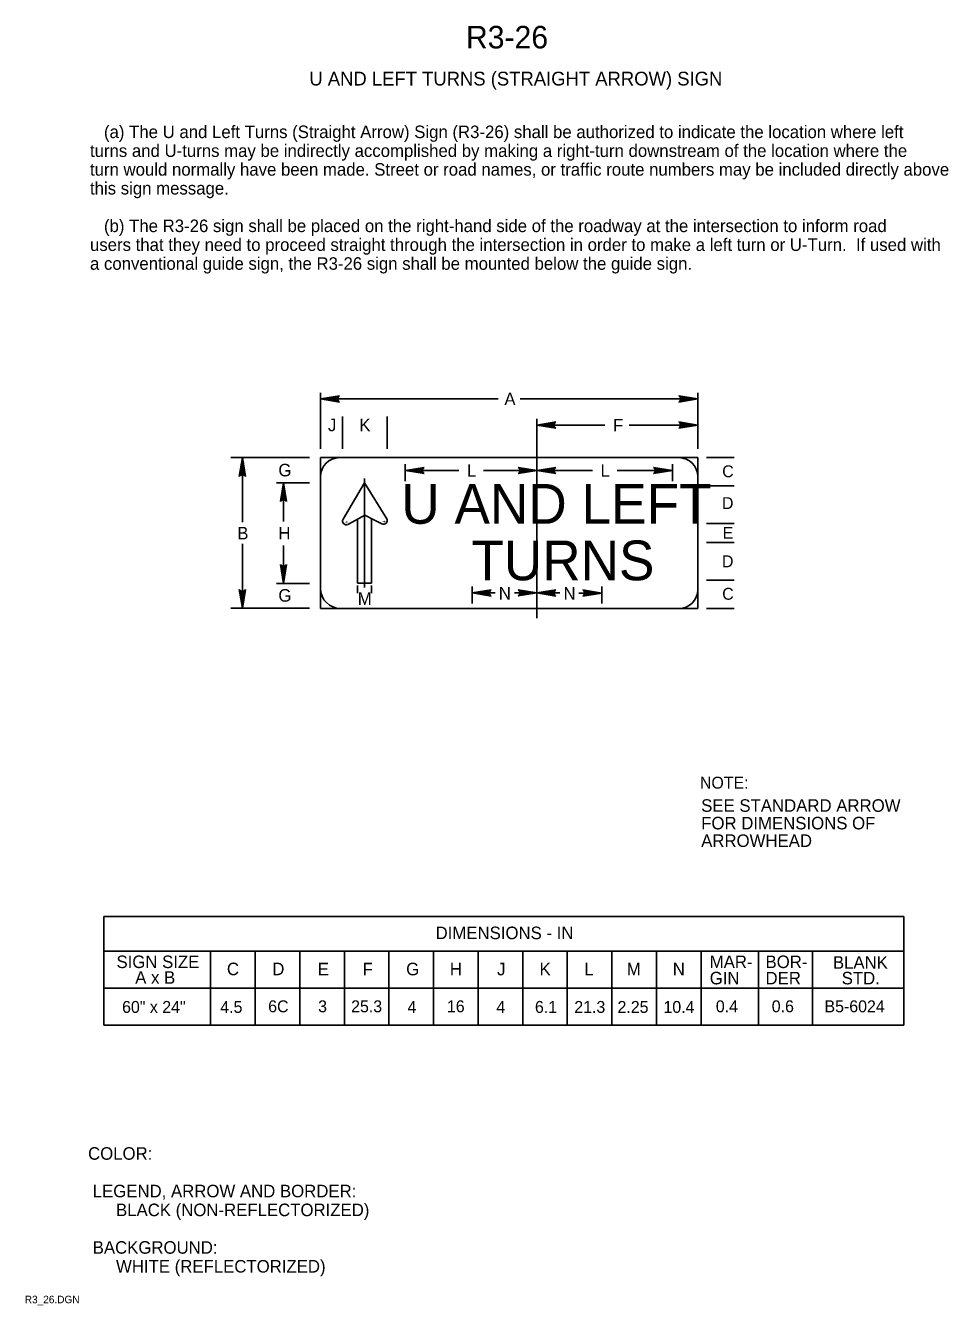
# Model space of a CAD drawing. Extents: x 0.5 to 7.7, y 0.2 to 10.2.
import ezdxf

# ---------------------------------------------------------------- set-up
doc = ezdxf.new("R2010")
doc.units = 0
for name, color, linetype in [('1', 7, 'Continuous'), ('11', 7, 'Continuous'), ('12', 7, 'Continuous'), ('2', 7, 'Continuous'), ('3', 7, 'Continuous')]:
    doc.layers.add(name, color=color, linetype=linetype)

# ---------------------------------------------------------------- blocks, each defined once
blk = doc.blocks.new('RARROW')
at = {"layer": '3'}
for p, q in [((-84.9, 11.2), (-89.2, 15.1)), ((-89.2, 15.1), (0, 0)), ((0, 0), (-89.2, -14.9)), ((-84.9, 11.2), (-81.7, 4.8)), ((0, 0), (-84.9, 11.2)), ((-84.6, -10.6), (0, 0)), ((-81.7, 4.8), (0, 0)), ((0, 0), (-81.7, -4.3)), ((-89.2, -14.9), (-84.6, -10.6)), ((-81.7, -4.3), (-84.6, -10.6))]:
    blk.add_line(p, q, dxfattribs=at)

msp = doc.modelspace()

# ---------------------------------------------------------------- linework, layer by layer
at = {"layer": '11'}
for p, q in [((2.814, 6.664), (2.814, 6.812)), ((2.962, 6.812), (2.814, 6.812)), ((5.627, 6.812), (5.775, 6.812)), ((5.775, 6.664), (5.775, 6.812)), ((2.814, 5.627), (2.814, 5.785)), ((5.775, 5.775), (5.775, 5.627)), ((2.972, 5.627), (2.814, 5.627)), ((5.627, 5.627), (5.775, 5.627))]:
    msp.add_line(p, q, dxfattribs=at)
at = {"layer": '12'}
for p, q in [((3.159, 6.615), (2.991, 6.328)), ((3.333, 6.331), (3.159, 6.615)), ((3.214, 6.332), (3.214, 5.825)), ((3.027, 6.288), (3.092, 6.322)), ((3.103, 6.328), (3.103, 5.825)), ((3.232, 6.323), (3.295, 6.292)), ((3.103, 5.825), (3.214, 5.825))]:
    msp.add_line(p, q, dxfattribs=at)
for centre, radius, start, end in [((3.309, 6.317), 0.0281, 241.8936, 29.8559), ((3.015, 6.313), 0.0282, 148.5633, 294.5639)]:
    msp.add_arc(centre, radius, start, end, dxfattribs=at)
at = {"layer": '3'}
for p, q in [((2.814, 7.032), (2.814, 7.322)), ((4.208, 7.273), (2.814, 7.273)), ((4.381, 7.273), (5.775, 7.273)), ((5.775, 6.959), (5.775, 7.322)), ((2.814, 6.881), (2.814, 7.117)), ((2.987, 6.881), (2.987, 7.134)), ((3.337, 6.881), (3.337, 7.134)), ((4.513, 6.959), (4.513, 7.117)), ((5.046, 7.068), (4.513, 7.068)), ((4.513, 7.039), (4.513, 5.552)), ((5.237, 7.068), (5.775, 7.068)), ((5.775, 6.881), (5.775, 7.072)), ((2.726, 6.812), (2.11, 6.812)), ((2.2, 6.306), (2.2, 6.812)), ((5.627, 6.812), (2.962, 6.812)), ((3.478, 6.628), (3.478, 6.76)), ((4.513, 6.642), (4.513, 6.76)), ((5.576, 6.628), (5.576, 6.76)), ((5.844, 6.812), (6.06, 6.812)), ((2.814, 6.664), (2.814, 5.785)), ((3.159, 6.647), (3.159, 5.791)), ((3.899, 6.711), (3.48, 6.711)), ((4.093, 6.711), (4.513, 6.711)), ((4.948, 6.711), (4.513, 6.711)), ((5.142, 6.711), (5.576, 6.711)), ((5.775, 5.775), (5.775, 6.664)), ((2.726, 6.615), (2.468, 6.615)), ((2.523, 6.311), (2.523, 6.615)), ((5.844, 6.59), (6.06, 6.59)), ((3.092, 6.322), (3.162, 6.36)), ((3.232, 6.323), (3.162, 6.36)), ((5.844, 6.294), (6.06, 6.294)), ((2.2, 6.134), (2.2, 5.629)), ((5.844, 6.146), (6.06, 6.146)), ((2.523, 6.122), (2.523, 5.824)), ((5.844, 5.849), (6.06, 5.849)), ((2.726, 5.824), (2.468, 5.824)), ((3.103, 5.809), (3.103, 5.749)), ((3.214, 5.808), (3.214, 5.747)), ((4.005, 5.666), (4.005, 5.799)), ((4.184, 5.75), (4.005, 5.75)), ((4.337, 5.75), (4.513, 5.75)), ((4.513, 5.681), (4.513, 5.799)), ((4.692, 5.75), (4.513, 5.75)), ((4.842, 5.749), (5.021, 5.749)), ((5.021, 5.666), (5.021, 5.799)), ((2.726, 5.629), (2.11, 5.629)), ((2.972, 5.627), (5.627, 5.627)), ((5.844, 5.627), (6.06, 5.627)), ((1.113, 3.208), (1.113, 2.356)), ((1.113, 3.208), (7.394, 3.208)), ((7.394, 3.208), (7.394, 2.356)), ((1.113, 2.937), (7.394, 2.937)), ((1.951, 2.937), (1.951, 2.356)), ((2.301, 2.937), (2.301, 2.356)), ((2.651, 2.937), (2.651, 2.356)), ((3.001, 2.937), (3.001, 2.356)), ((3.351, 2.937), (3.351, 2.356)), ((3.701, 2.937), (3.701, 2.356)), ((4.051, 2.937), (4.051, 2.356)), ((4.401, 2.937), (4.401, 2.356)), ((4.751, 2.937), (4.751, 2.356)), ((5.101, 2.937), (5.101, 2.356)), ((5.451, 2.937), (5.451, 2.356)), ((5.801, 2.937), (5.801, 2.356)), ((6.251, 2.937), (6.251, 2.356)), ((6.677, 2.937), (6.677, 2.356)), ((1.113, 2.647), (7.394, 2.647)), ((1.113, 2.356), (7.394, 2.356))]:
    msp.add_line(p, q, dxfattribs=at)
for centre, radius, start, end in [((2.962, 6.664), 0.148, 90, 180), ((5.627, 6.664), 0.148, 0, 90), ((2.972, 5.785), 0.158, 180, 270), ((5.627, 5.775), 0.148, 270, 0)]:
    msp.add_arc(centre, radius, start, end, dxfattribs=at)

# ---------------------------------------------------------------- block references
at = {"layer": '3', "xscale": 0.0016545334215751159, "yscale": 0.0016366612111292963}
for p, rotation in [((2.814, 7.273), 180), ((4.513, 7.068), 180), ((2.2, 6.812), 90), ((3.48, 6.711), 180), ((4.513, 6.711), 180), ((2.523, 6.615), 90), ((2.523, 5.824), -90), ((2.2, 5.629), -90), ((4.005, 5.75), 180), ((4.513, 5.75), 180)]:
    msp.add_blockref('RARROW', p, dxfattribs=dict(at, rotation=rotation))
for p in [(5.775, 7.273), (5.775, 7.068), (4.513, 6.711), (5.576, 6.711), (4.513, 5.75), (5.021, 5.749)]:
    msp.add_blockref('RARROW', p, dxfattribs=at)

# ---------------------------------------------------------------- texts
at = {"layer": '1'}
for s, height, p in [('R3-26', 0.1772, (3.955, 10.025)), ('U AND LEFT TURNS (STRAIGHT ARROW) SIGN', 0.10828, (2.726, 9.734)), ('NOTE:', 0.0935, (5.792, 4.213)), ('SEE STANDARD ARROW', 0.09842, (5.802, 4.031)), ('FOR DIMENSIONS OF', 0.09842, (5.802, 3.893)), ('ARROWHEAD', 0.0984, (5.802, 3.755)), ('COLOR:', 0.0984, (0.989, 1.299)), (' LEGEND, ARROW AND BORDER:', 0.09842, (0.989, 1.004)), ('      BLACK (NON-REFLECTORIZED)', 0.09842, (0.989, 0.856)), (' BACKGROUND:', 0.09842, (0.989, 0.561)), ('      WHITE (REFLECTORIZED)', 0.09842, (0.989, 0.413)), ('R3_26.DGN', 0.0591, (0.492, 0.172))]:
    msp.add_text(s, height=height, dxfattribs=at).set_placement(p)
at = {"layer": '12'}
for s, height, p in [('U AND LEFT', 0.3121, (3.448, 6.293)), ('TURNS', 0.312, (3.998, 5.849))]:
    msp.add_text(s, height=height, dxfattribs=at).set_placement(p)
msp.add_text('+', height=0.031, rotation=90.5834, dxfattribs=at).set_placement((3.03, 6.294))
at = {"layer": '2'}
for s, height, p in [('   (a) The U and Left Turns (Straight Arrow) Sign (R3-26) shall be authorized to indicate the location where left ', 0.098415, (1.004, 9.321)), ('turns and U-turns may be indirectly accomplished by making a right-turn downstream of the location where the ', 0.098415, (1.004, 9.173)), ('turn would normally have been made. Street or road names, or traffic route numbers may be included directly above ', 0.098415, (1.004, 9.026)), ('this sign message.', 0.09842, (1.004, 8.878)), ('   (b) The R3-26 sign shall be placed on the right-hand side of the roadway at the intersection to inform road ', 0.098415, (1.004, 8.583)), ('users that they need to proceed straight through the intersection in order to make a left turn or U-Turn.  If used with ', 0.098415, (1.004, 8.435)), ('a conventional guide sign, the R3-26 sign shall be mounted below the guide sign.', 0.09842, (1.004, 8.287))]:
    msp.add_text(s, height=height, dxfattribs=at).set_placement(p)
at = {"layer": '3'}
for s, height, p in [('A', 0.0984, (4.257, 7.224)), ('J', 0.0984, (2.872, 7.019)), ('K', 0.0984, (3.118, 7.019)), ('F', 0.0984, (5.11, 7.018)), ('G', 0.0984, (2.483, 6.665)), ('L', 0.0984, (3.964, 6.662)), ('L', 0.0984, (5.012, 6.662)), ('C', 0.0935, (5.967, 6.658)), ('D', 0.0935, (5.965, 6.408)), ('B', 0.0984, (2.16, 6.17)), ('H', 0.0984, (2.483, 6.17)), ('E', 0.0935, (5.97, 6.175)), ('D', 0.0935, (5.965, 5.951)), ('G', 0.0984, (2.483, 5.681)), ('M', 0.0984, (3.106, 5.656)), ('N', 0.0984, (4.213, 5.698)), ('N', 0.0984, (4.721, 5.697)), ('C', 0.0935, (5.967, 5.696)), ('DIMENSIONS - IN', 0.09842, (3.717, 3.031)), ('SIGN SIZE', 0.0984, (1.212, 2.804)), ('C', 0.0984, (2.079, 2.748)), ('D', 0.0984, (2.435, 2.748)), ('E', 0.0984, (2.792, 2.747)), ('F', 0.0984, (3.144, 2.747)), ('G', 0.0984, (3.486, 2.747)), ('H', 0.0984, (3.829, 2.747)), ('J', 0.0984, (4.2, 2.747)), ('K', 0.0984, (4.533, 2.747)), ('L', 0.0984, (4.885, 2.747)), ('M', 0.0984, (5.218, 2.747)), ('N', 0.0984, (5.579, 2.747)), ('MAR-', 0.0984, (5.869, 2.804)), ('BOR-', 0.0984, (6.307, 2.804)), ('BLANK', 0.0984, (6.836, 2.799)), ('A x B', 0.0984, (1.359, 2.681)), ('GIN', 0.0984, (5.869, 2.676)), ('DER', 0.0984, (6.307, 2.676)), ('STD.', 0.0984, (6.905, 2.676)), ('60" x 24"', 0.0935, (1.256, 2.452)), ('4.5', 0.0935, (2.027, 2.452)), ('6C', 0.0935, (2.403, 2.457)), ('3', 0.0935, (2.795, 2.457)), ('25.3', 0.0935, (3.054, 2.457)), ('4', 0.0935, (3.497, 2.452)), ('16', 0.0935, (3.806, 2.457)), ('4', 0.0935, (4.194, 2.452)), ('6.1', 0.0935, (4.497, 2.452)), ('21.3', 0.0935, (4.806, 2.452)), ('2.25', 0.0935, (5.145, 2.452)), ('10.4', 0.0935, (5.506, 2.452)), ('0.4', 0.0935, (5.917, 2.457)), ('0.6', 0.0935, (6.356, 2.457)), ('B5-6024', 0.0935, (6.77, 2.457))]:
    msp.add_text(s, height=height, dxfattribs=at).set_placement(p)
msp.add_text('+', height=0.031, rotation=90.6926, dxfattribs=at).set_placement((3.328, 6.297))

doc.saveas('drawing.dxf')
